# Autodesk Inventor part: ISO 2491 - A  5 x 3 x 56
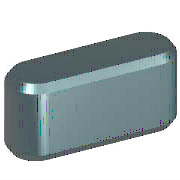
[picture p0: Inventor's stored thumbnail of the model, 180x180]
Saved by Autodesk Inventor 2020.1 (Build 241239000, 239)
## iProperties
Created: 2019-01
Part Number: ISO 2491 - A  5 x 3 x 56
Material: Stahl, weich
Description: Passfedern
Document SubType Name: Modeling
Standard: ISO 2491
Designer: lutzd
Standard Revision: First edition 1974-08-15
Standards Organization: ISO
Language: de-DE
Size Designation: A  5 x 3 x 56
Categories: <MemberInstance><Categories><Category DisplayName="Wellenteile" InternalName="7f7aeb1f-a693-4053-b835-cee3144e0d98" Mnemonic="SHFT"><Category DisplayName="Passf
Mass: 6.32086 g
Surface Area: 8.46816 cm^2
Volume: 0.805206 cm^3
Density: 7.85 g/cm^3
Appearance: Semi-Polished(8)
IsCustomPart: 0
Author: lutzd
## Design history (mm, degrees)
workplane "Work Plane1"
workplane "Work Plane2"
sketch "Skizze1"
  geometry: L1 (2.5, 2.5)-(53.5, 2.5); L2 (53.5, -2.5)-(2.5, -2.5); L3 (0, 9.4)-(0, -7.4) reference; L4 (-5, 0)-(30, 0) reference; L5 (56, 0)-(56, 7); A1 r 2.5 centre (2.5, 0) between (2.5, 2.5) and (2.5, -2.5); A2 r 2.5 centre (53.5, 0) between (53.5, -2.5) and (53.5, 2.5)
  constraints: 6 end point, 5 point on circle, 4 tangent, 3 point on line, 2 centre point, 1 horizontal, 1 parallel, 1 perpendicular
  dimensions: "d0" = 2.5 radius of A1 (= 0.5 x PB); "d13" = 2.5 radius of A2 (= 0.5 x PB); "d14" = 56 distance between parallel lines of L5 L3 (= NLG)
extrude "Körper1" new body sketch "Skizze1" taper "d3" = 0 deg; stored distance "d4" = 10
workplane "Work Plane3"
body "Solid1"
chamfer "Fase1" distance "d8" = 0.4 (= PHH); stored, may be unused: second distance "d9" = 0.4 (= PHH), angle "d15" = 45 deg
other parameters: "d1" = -1.8 (= -PNT), "d2" = 1.2 (= PH - PNT), "NLG" = 56 [user parameter; used in 1 equation term], "PB" = 5 [user parameter; used in 2 equation terms], "PNT" = 1.8 [user parameter; used in 2 equation terms], "PH" = 3 [user parameter; used in 1 equation term], "PHH" = 0.4 [user parameter; used in 2 equation terms], "d10" = 0, "d16" = 0, "d17" = 0, "d18" = 0, "RR" = 0.16 [user parameter], "WDMIN" = 12 [user parameter], "WDMAX" = 17 [user parameter], "PLB1" = 56 [user parameter], "PLB2" = 56 [user parameter], "PUEB" = 1.4 [user parameter]
